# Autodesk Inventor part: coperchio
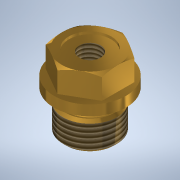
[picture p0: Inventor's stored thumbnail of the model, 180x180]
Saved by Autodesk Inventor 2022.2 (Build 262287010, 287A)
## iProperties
Created: 2014-01
Part Number: coperchio
Document SubType Name: Modeling
Designer: UTENTE
Density: 8.47 g/cm^3
Material: Ottone, Giallo chiaro
Appearance: Ottone - Satinato
Author: UTENTE
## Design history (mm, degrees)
sketch "Schizzo1"
  geometry: C1 r 12.7 at (0, 0); 1 further point
  constraints: 1 centre point, 1 coincident
  dimensions: "d0" = 25.4 diameter of C1
extrude "Estrusione1" new body sketch "Schizzo1" distance "d1" = 9; taper "d2" = 0 deg
chamfer "Smusso1" distance "d3" = 1; stored, may be unused: second distance "d4" = 1.7, angle "d5" = 30 deg
sketch "Schizzo2"
  geometry: L1 (-11, 6.351)-(0, 12.702); L2 (0, 12.702)-(11, 6.351); L3 (11, 6.351)-(11, -6.351); L4 (11, -6.351)-(0, -12.702); L5 (0, -12.702)-(-11, -6.351); L6 (-11, -6.351)-(-11, 6.351); C1 r 16.553 at (0, 0); 2 further points
  constraints: 12 end point, 1 centre point, 1 coincident, 1 midpoint, 13 other
extrude "Estrusione2" cut sketch "Schizzo2" distance "d6" = 9; taper "d7" = 0 deg
sketch "Schizzo3"
  geometry: C1 r 14 at (0, 0); A1 r 12.7 centre (0, 0) between (10.997, -6.353) and (11, -6.347) reference
  constraints: 1 centre point, 1 coincident
extrude "Estrusione3" join sketch "Schizzo3" distance "d9" = 4; taper "d10" = 0 deg
sketch "Schizzo4"
  geometry: C1 r 14 at (0, 0) reference; C2 r 8.5 at (0, 0)
  constraints: 1 centre point, 1 coincident
extrude "Estrusione4" join sketch "Schizzo4" distance "d12" = 4; taper "d13" = 0 deg
sketch "Schizzo5"
  geometry: C1 r 8.5 at (0, 0) reference; C2 r 10.477 at (0, 0)
  constraints: 1 centre point, 1 coincident
  dimensions: "d14" = 20.955 diameter of C2
extrude "Estrusione5" join sketch "Schizzo5" distance "d15" = 11; taper "d16" = 0 deg
chamfer "Smusso2" distance "d17" = 1; stored, may be unused: second distance "d18" = 1.7, angle "d19" = 30 deg
feature "Filettatura1" dims "d20" = 10, "d21" = 0
fillet "Raccordo1" dims "d22" = 0.5
sketch "Schizzo6"
  geometry: C1 r 8.25 at (0, 0); A1 r 11 centre (0, 0) between (-5.5, -9.526) and (5.5, -9.526) reference
  constraints: 1 centre point, 1 coincident
extrude "Estrusione6" cut sketch "Schizzo6" distance "d24" = 1; taper "d25" = 0 deg
sketch "Schizzo7"
  geometry: C1 r 8.25 at (0, 0) reference
hole "Hole1" diameter "d28" = 8.376; stored, may be unused: countersink angle "d32" = 90 deg, drill point angle "d34" = 118 deg; dims "d26" = 10, "d27" = 10, "d29" = 6, "d30" = 4, "d31" = 2, "d33" = 40
chamfer "Smusso3" distance "d35" = 1; stored, may be unused: second distance "d36" = 2, angle "d37" = 45 deg
node "Solido1"
